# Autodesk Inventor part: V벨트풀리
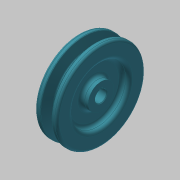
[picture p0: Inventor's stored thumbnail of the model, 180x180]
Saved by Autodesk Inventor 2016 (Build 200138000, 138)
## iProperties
Created: 2015-11
Part Number: V벨트풀리
Material: 강철, 탄소
Document SubType Name: Modeling
Designer: mduedu
Density: 1 g/cm^3
Appearance: 커뎃 파란색
Author: mduedu
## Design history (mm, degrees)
sketch "스케치1"
  geometry: L1 (-9.5, 0)-(9.5, 0); L2 (0, 0)-(0, 37.7); L3 (-4.825, 37.7)-(-9.5, 37.7); L4 (-9.5, 37.7)-(-9.5, 0); L5 (0, 28.7)-(-2.074, 28.7); L6 (-2.074, 28.7)-(-4.825, 37.7); L7 (4.825, 37.7)-(9.5, 37.7); L8 (9.5, 37.7)-(9.5, 0); L9 (0, 28.7)-(2.074, 28.7); L10 (2.074, 28.7)-(4.825, 37.7); L11 (-9.5, 35)-(9.5, 35); 3 further points
  constraints: 22 end point, 7 point on line, 4 perpendicular, 3 symmetric about line, 1 coincident, 1 horizontal, 1 horizontal alignment, 1 midpoint, 1 vertical
  dimensions: "d0" = 19 distance of L1.start L1.end; "d2" = 75.4 diameter of L2.end L1 (derived); "d3" = 34 deg angle of L10 L6; "d4" = 6.3 distance between parallel lines of L11 L9; "d5" = 2.7 distance between parallel lines of L7 L11; "d6" = 8 distance of point (4, 35) point (-4, 35); "d7" = 70 diameter of L11 L1
revolve "회전1" sketch "스케치1" stored, may be unused: angle "d8" = 90 deg
sketch "스케치2"
  geometry: C1 r 24 at (0, 0); C2 r 11 at (0, 0); 1 further point
  constraints: 2 centre point, 2 coincident
  dimensions: "d9" = 48 diameter of C1; "d10" = 22 diameter of C2
extrude "돌출1" cut sketch "스케치2" distance "d11" = 6; taper "d12" = 0 deg
fillet "모깎기1" dims "d13" = 3
fillet "모깎기2" dims "d14" = 3
fillet "모깎기3" dims "d15" = 1, "d16" = 0.5, "d17" = 2
hole "구멍1" diameter "d20" = 10; stored, may be unused: countersink angle "d24" = 90 deg, drill point angle "d26" = 118 deg; dims "d18" = 10, "d19" = 10, "d21" = 6, "d22" = 4, "d23" = 2, "d25" = 8
sketch "스케치3"
  geometry: L1 (-1.5, 0)-(1.5, 0); L2 (1.5, 0)-(1.5, 6.4); L3 (1.5, 6.4)-(-1.5, 6.4); L4 (-1.5, 6.4)-(-1.5, 0); 2 further points
  constraints: 8 end point, 2 parallel, 1 coincident, 1 horizontal, 1 midpoint, 1 perpendicular
  dimensions: "d27" = 3 distance of L2.end L3.end; "d29" = 6.4 distance of L3.end L1.start
extrude "돌출2" cut sketch "스케치3" stored distance "d30" = 6; taper "d31" = 0 deg
chamfer "모따기1" distance "d32" = 0.5; stored, may be unused: second distance "d33" = 2, angle "d34" = 45 deg
node "솔리드1"
mirror "대칭1"
